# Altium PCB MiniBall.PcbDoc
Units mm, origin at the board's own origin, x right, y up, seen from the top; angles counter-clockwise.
Board outline 43 x 55 mm, 4 copper layers (Top Layer, Plane 1, Plane 2, Bottom Layer), stack 0.781 mm thick; 44 components, 24 nets, 153 pads, 113 vias.
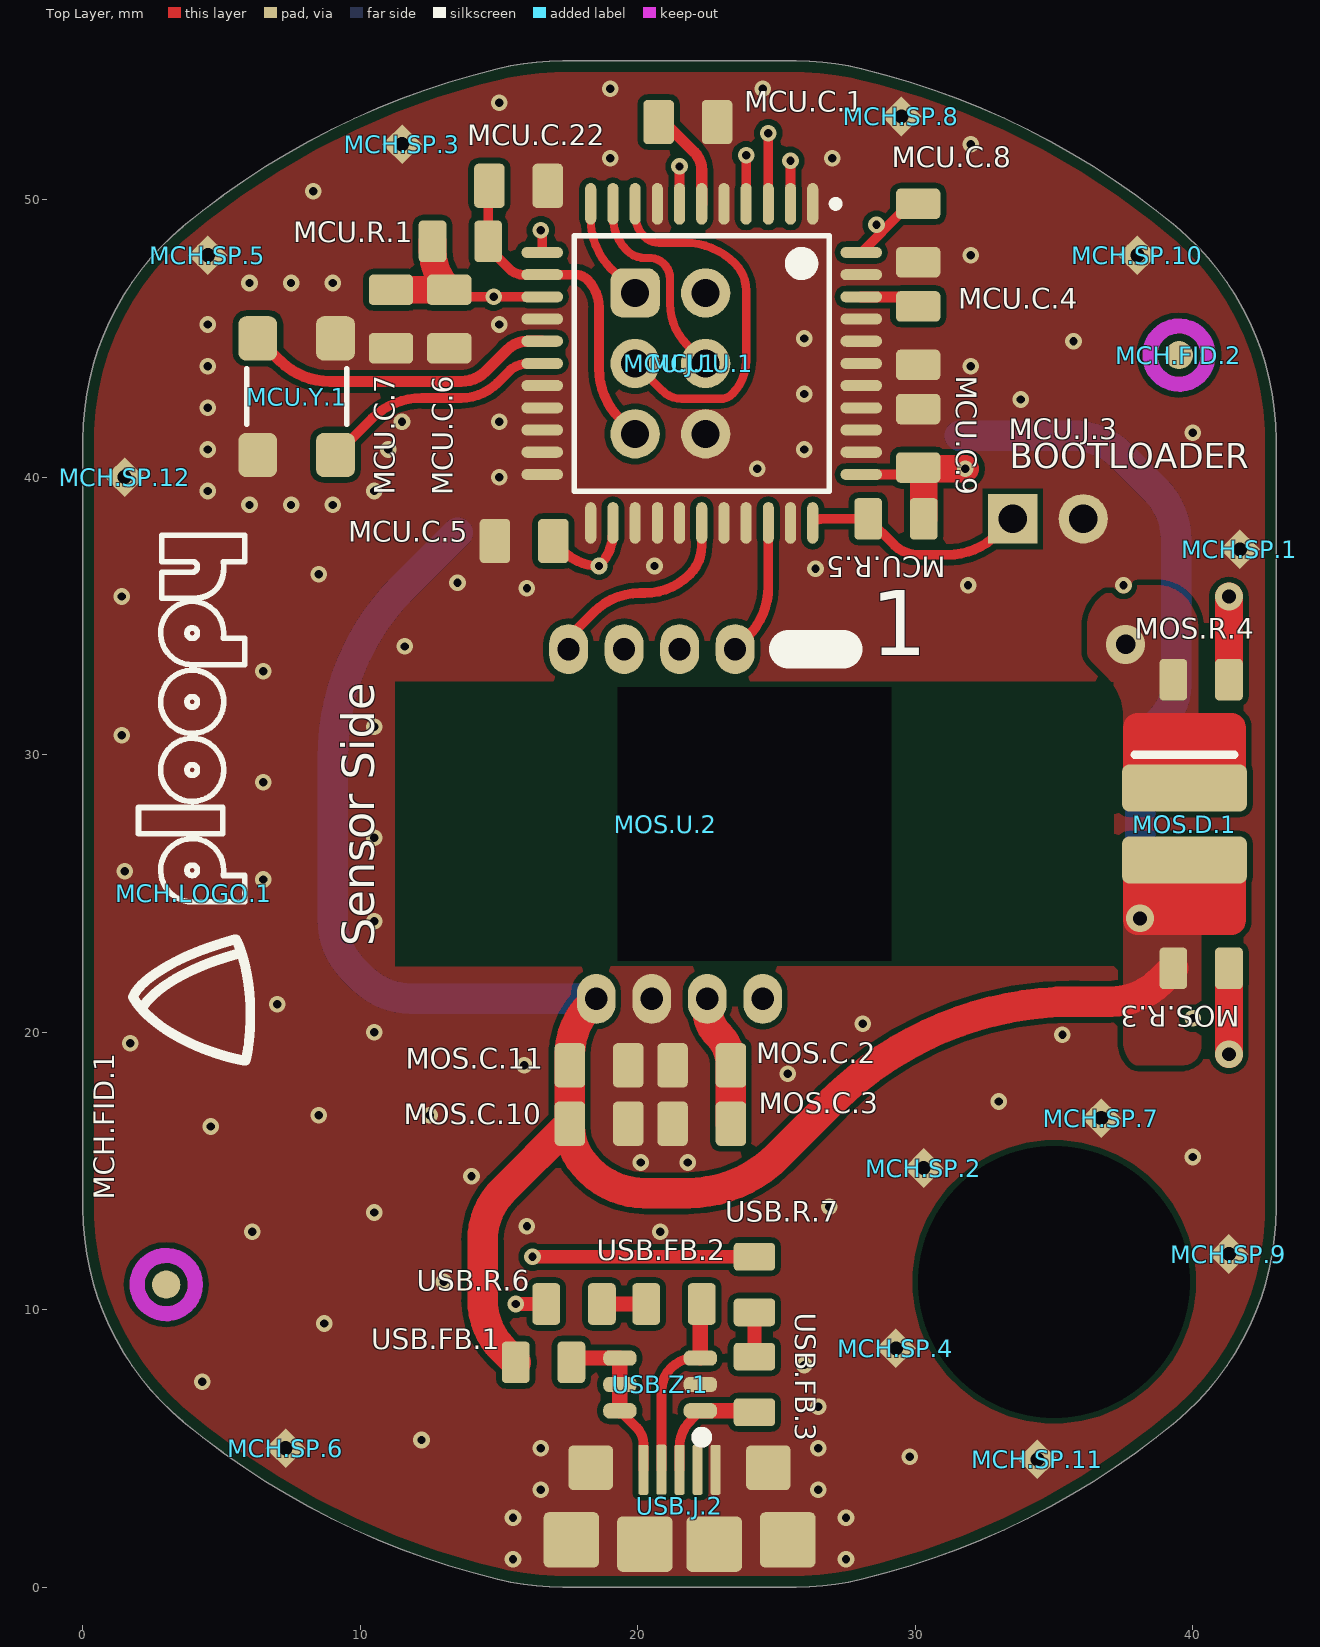
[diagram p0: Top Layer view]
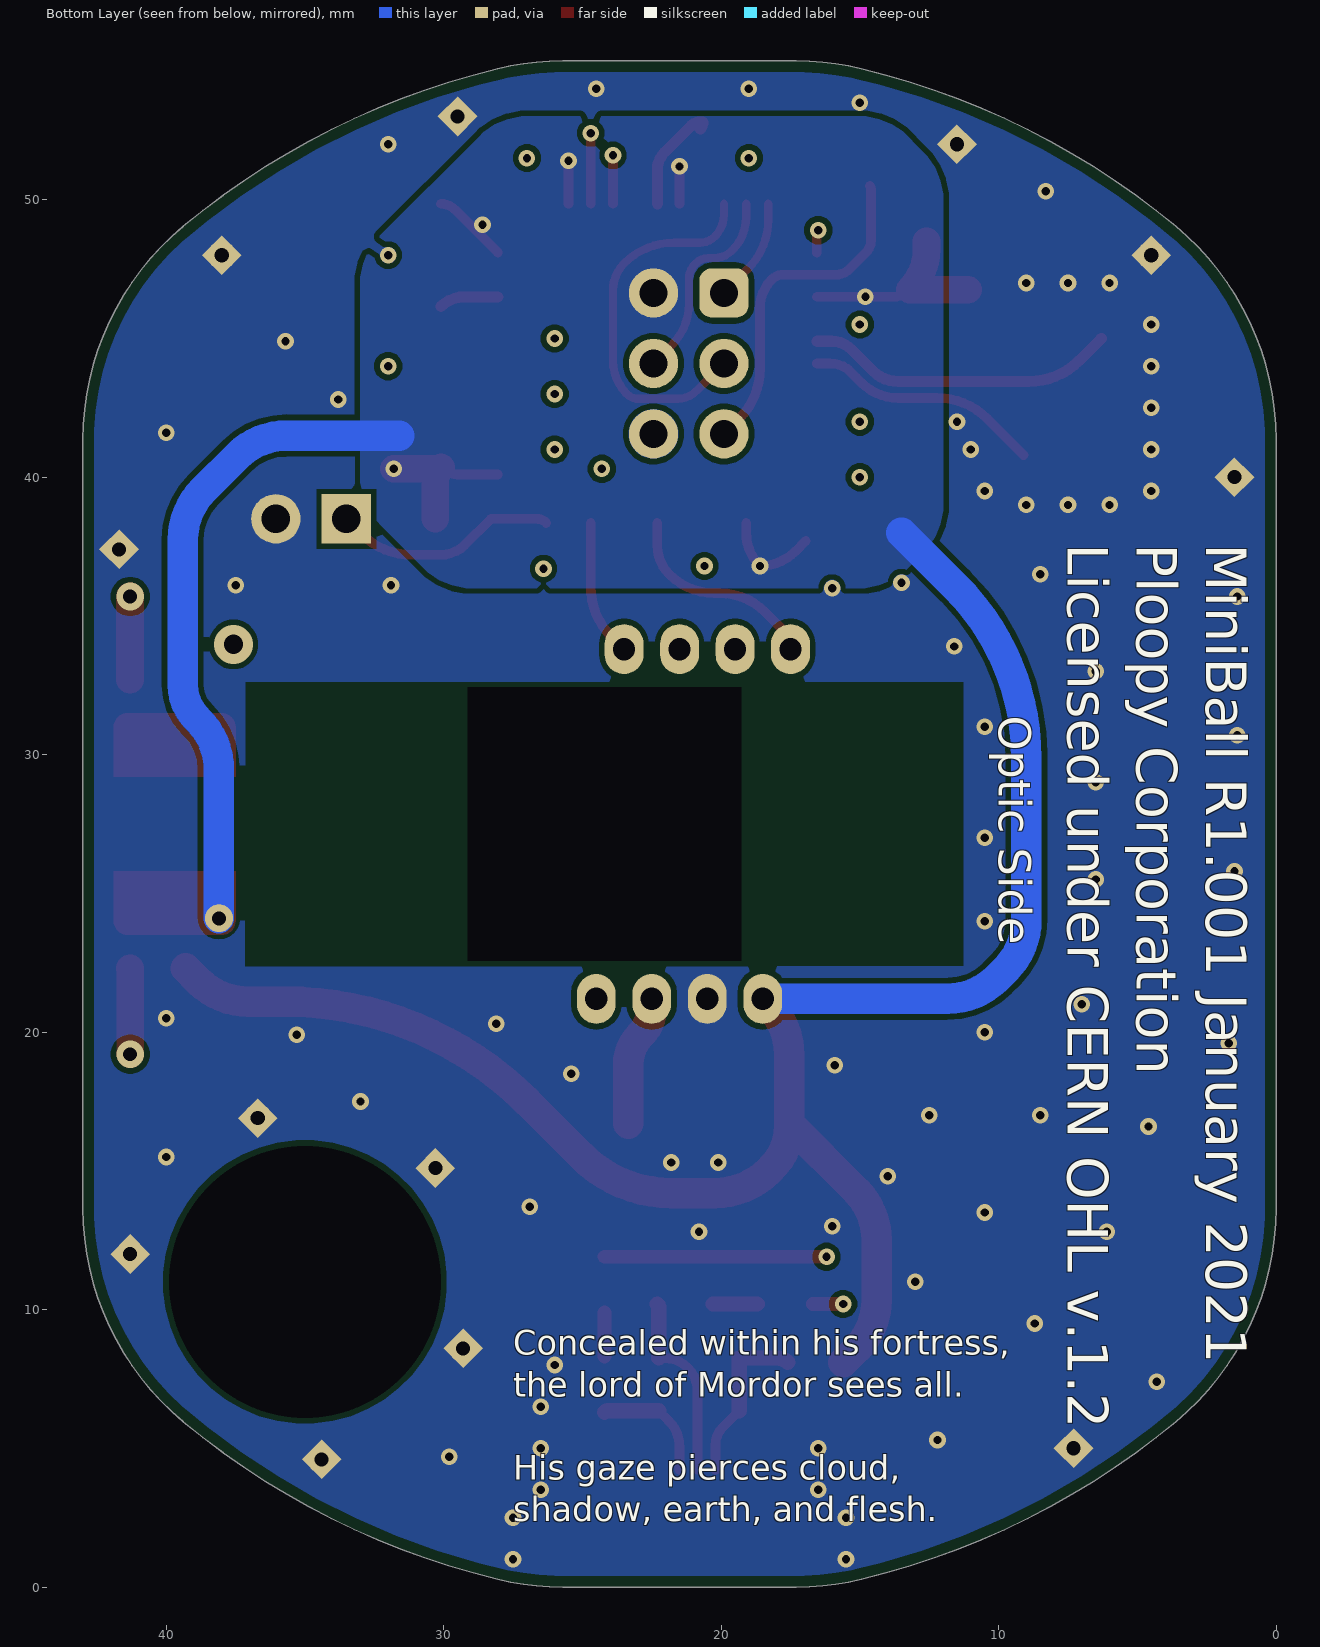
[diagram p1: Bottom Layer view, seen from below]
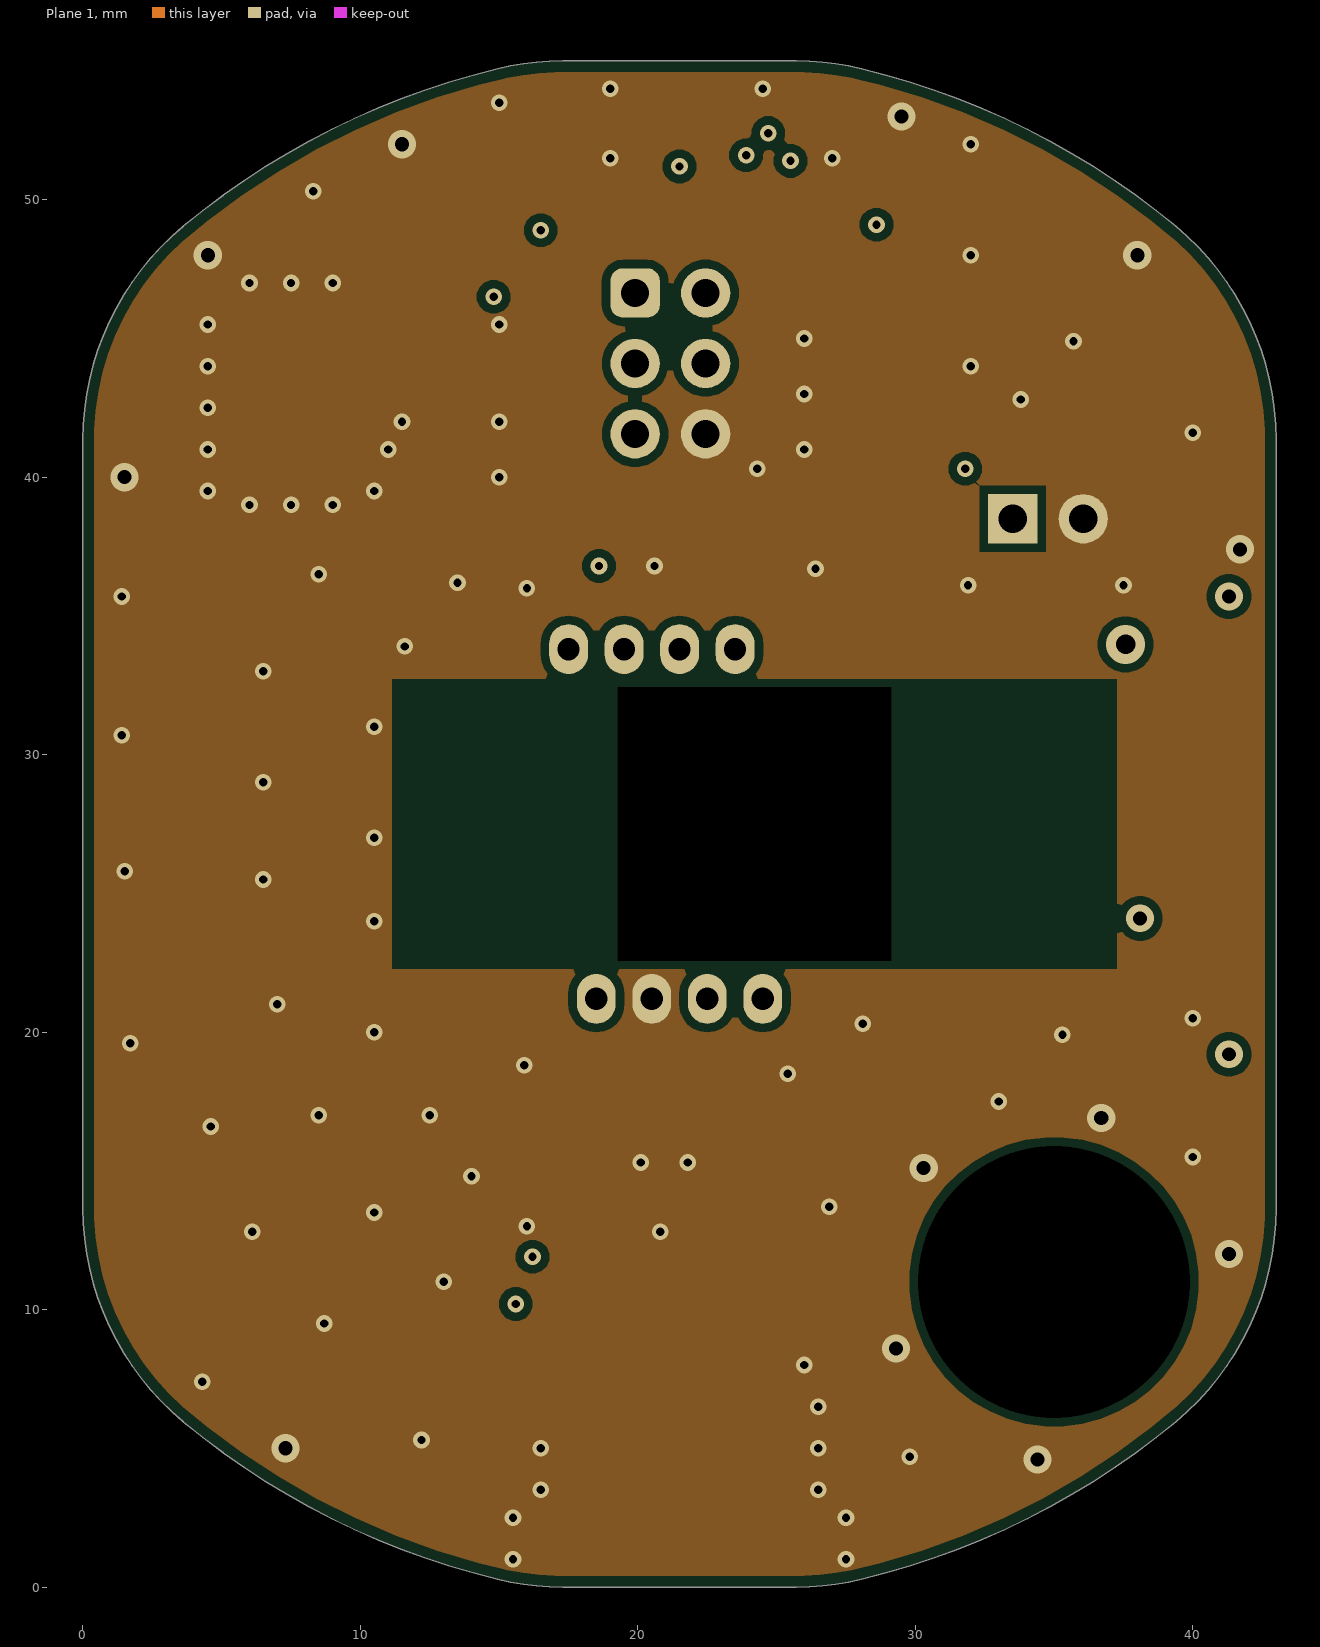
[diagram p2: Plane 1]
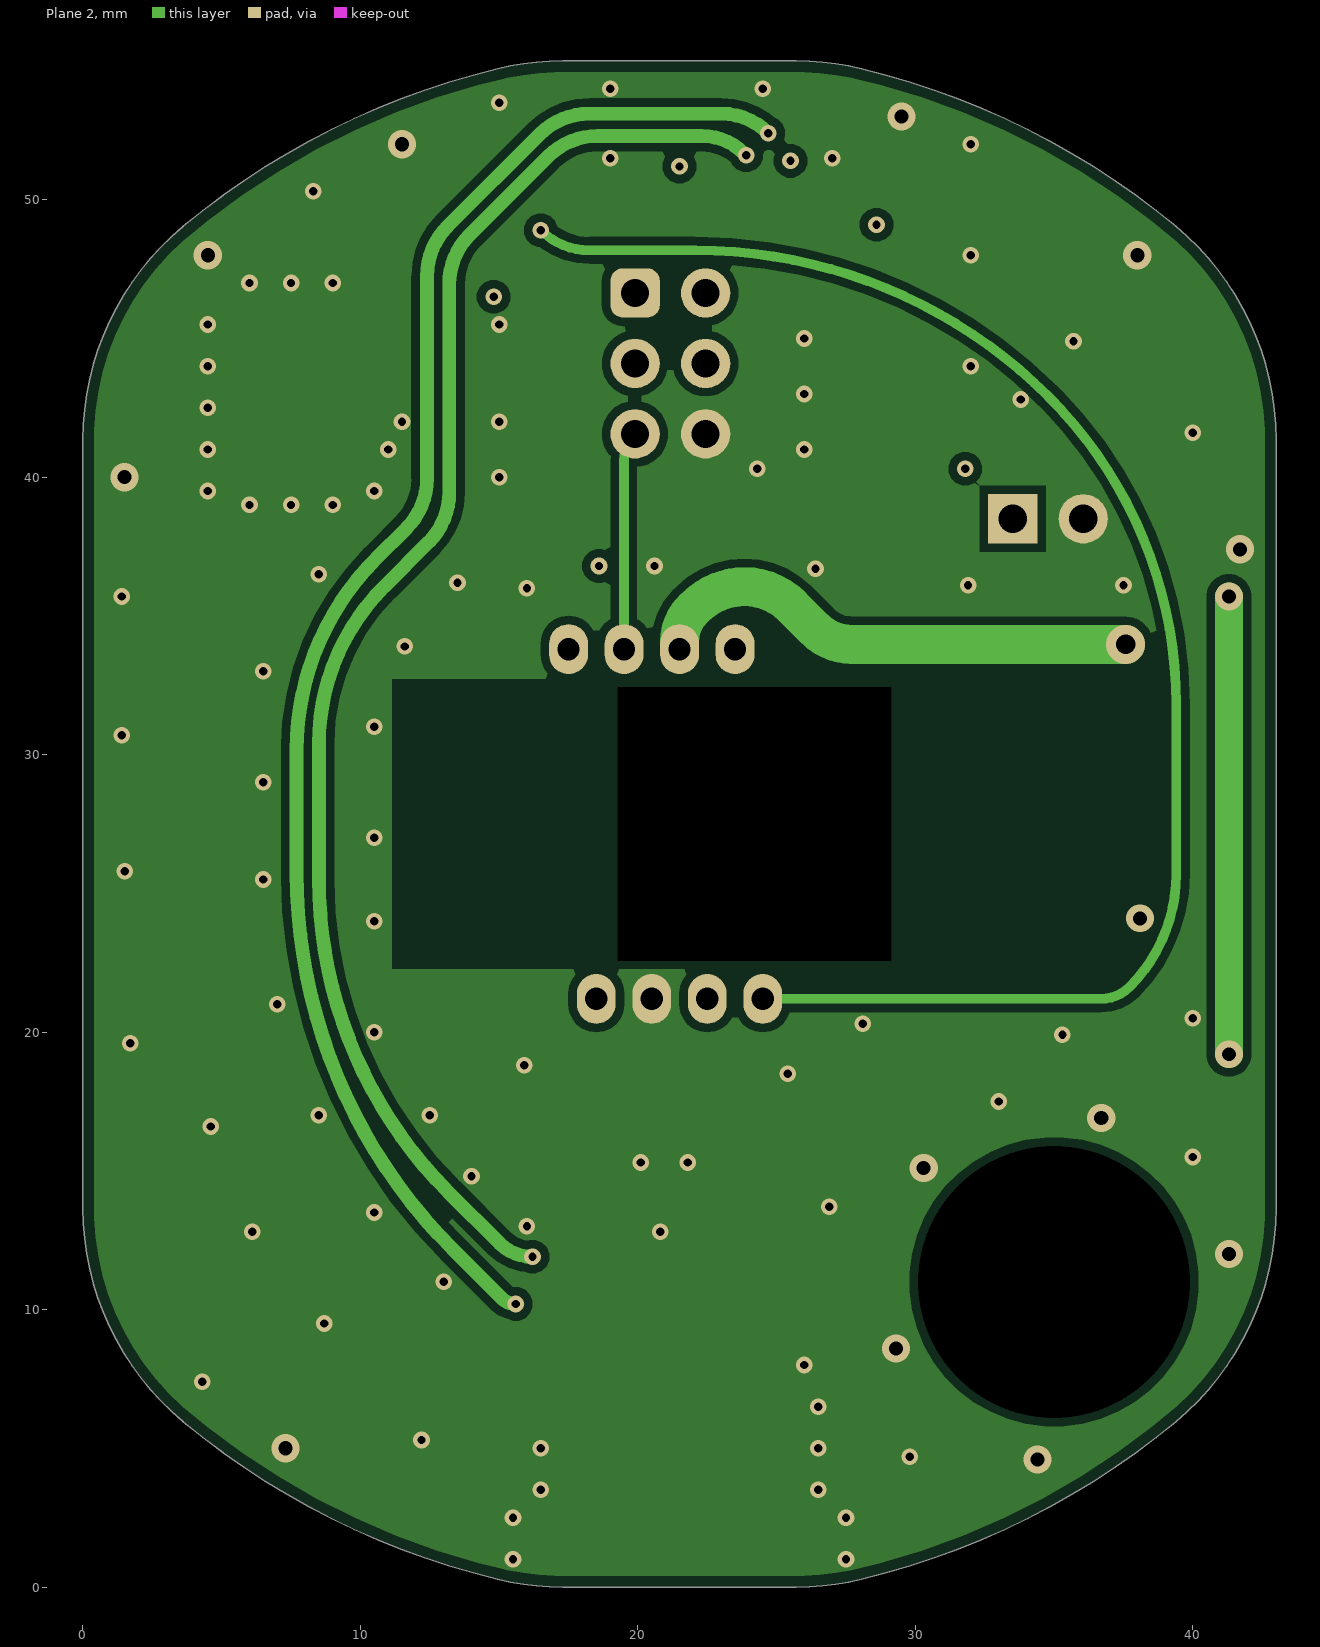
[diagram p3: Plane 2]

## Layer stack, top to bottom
Top Mask: solder mask 0.01, Solder Resist, Dk 3.5
Top Layer: signal copper 0.036
Dielectric 1: prepreg 0.127, FR-4, Dk 4.2
Plane 1: signal copper 0.036
Dielectric 4: core 0.383, Dk 4.2
Plane 2: signal copper 0.036
Dielectric 2: prepreg 0.127, Dk 4.2
Bottom Layer: signal copper 0.036
Bottom Solder: solder mask 0.01, Solder Resist, Dk 3.5

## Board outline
3.611,5.96 ccw(c21.5,27.5) 14.946,0.278 ccw(c17.287,10) 17.287,0 25.713,0 ccw(c25.713,10) 28.054,0.278 ccw(c21.5,27.5) 39.389,5.96 ccw(c33,13.653) 43,13.653 43,41.347 ccw(c33,41.347) 39.389,49.04 ccw(c21.5,27.5) 28.054,54.722 ccw(c25.713,45) 25.713,55 17.287,55 ccw(c17.287,45) 14.946,54.722 ccw(c21.5,27.5) 3.611,49.04 ccw(c10,41.347) 0,41.347 0,13.653 ccw(c10,13.653)

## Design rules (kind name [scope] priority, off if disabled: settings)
BoardOutlineClearance [(Not HasFootprint('SPARKGAP'))] p1: gap=0.4 ignorepadtopadclearanceinfootprint=FALSE except(0: Arc-SplitBarrior Arc-SplitContinuation Track-SplitBarrior Track-SplitContinuation SMDPad-SplitBarrior SMDPad-SplitContinuation THPad-SplitBarrior THPad-SplitContinuation Via-SplitBarrior Via-SplitContinuation Fill-SplitBarrior Fill-SplitContinuation Poly-SplitBarrior Poly-SplitContinuation Region-SplitBarrior Region-SplitContinuation Text-SplitBarrior Text-SplitContinuation)
Clearance "HighV Pads" [(InNetClass('HighV') AND (IsPad OR IsVia)) vs IsPad OR IsVia] p1: gap=0.4 ignorepadtopadclearanceinfootprint=FALSE except(0: Arc-Hole Track-Hole SMDPad-Hole THPad-Hole Via-Hole Fill-Hole Poly-Hole Region-Hole Text-Hole) // Establishes minimum clearance between bare pads that are high voltage, per IPC2221A Table 6-1, 51-100V, condition A6
Clearance Inter-Pad [IsPad vs IsPad] p2: gap=0.2 ignorepadtopadclearanceinfootprint=FALSE except(0: Arc-Hole Track-Hole SMDPad-Hole THPad-Hole Via-Hole Fill-Hole Poly-Hole Region-Hole Text-Hole)
Clearance "Spark Gaps" [InNetClass('Spark Gap') vs InNet('GND') And InPoly] p3: gap=0.635 ignorepadtopadclearanceinfootprint=FALSE except(0: Arc-Hole Track-Hole SMDPad-Hole THPad-Hole Via-Hole Fill-Hole Poly-Hole Region-Hole Text-Hole)
Clearance FIDs [Name like 'FID*'] p4: gap=1.016 ignorepadtopadclearanceinfootprint=FALSE except(0: Arc-Hole Track-Hole SMDPad-Hole THPad-Hole Via-Hole Fill-Hole Poly-Hole Region-Hole Text-Hole)
Clearance "Inner Planes" [InPoly AND OnMid] p5: gap=0.3 ignorepadtopadclearanceinfootprint=FALSE except(0: Arc-Hole Track-Hole SMDPad-Hole THPad-Hole Via-Hole Fill-Hole Poly-Hole Region-Hole Text-Hole) // Defines a larger clearance for planes on inner layers.
Clearance "All Planes" [InPoly] p6: gap=0.2 ignorepadtopadclearanceinfootprint=FALSE except(0: Arc-Hole Track-Hole SMDPad-Hole THPad-Hole Via-Hole Fill-Hole Poly-Hole Region-Hole Text-Hole) // Defines minimum clearance between planes on the same layer.
Clearance "Inner Layer Clearance" [OnMid vs OnMid] p7: gap=0.22 ignorepadtopadclearanceinfootprint=FALSE // We will give inner layers more spacing because they tend to be subject to stricter process limits.
Clearance [All] p8: gap=0.22 ignorepadtopadclearanceinfootprint=FALSE except(0: Arc-Hole Track-Hole SMDPad-Hole THPad-Hole Via-Hole Fill-Hole Poly-Hole Region-Hole Text-Hole) // 2 oz (70um) boards require at least 10mil spacing. We give a bit more to make sure things work well.
ComponentClearance "Terminal Block" [(HasFootprint('Phoenix 1933189 - Header')) vs (HasFootprint('Phoenix 1933189 - Header'))] p1: gap=-2.286 collisioncheckmode=3 verticalgap=0.254 showdistances=FALSE
ComponentClearance "FET/TP self Clearance" [(Name like 'Q*') Or (Name like 'TP*') vs (Name like 'Q*') Or (Name like 'TP*')] p2: gap=0.254 collisioncheckmode=3 verticalgap=0.254 showdistances=FALSE
ComponentClearance [Not ((Name like 'H*') Or (Name like 'FID*') Or (Name like 'SP*')) vs Not ((Name like 'H*') Or (Name like 'FID*') Or (Name like 'SP*'))] p3: gap=0.5 collisioncheckmode=3 verticalgap=0.5 showdistances=FALSE
DiffPairsRouting [All] p1: maxlimit=0.508 minlimit=0.279 mostfreqgap=0.381 substack1={769A8C6D-1C2C-4ABD-9F78-73D1337B8DA3} toplayer_{769a8c6d-1c2c-4abd-9f78-73d1337b8da3}_minwidth=0.381 toplayer_{769a8c6d-1c2c-4abd-9f78-73d1337b8da3}_maxwidth=0.381 toplayer_{769a8c6d-1c2c-4abd-9f78-73d1337b8da3}_prefwidth=0.381 midlayer2_{769a8c6d-1c2c-4abd-9f78-73d1337b8da3}_minwidth=0.381 midlayer2_{769a8c6d-1c2c-4abd-9f78-73d1337b8da3}_maxwidth=0.381 midlayer2_{769a8c6d-1c2c-4abd-9f78-73d1337b8da3}_prefwidth=0.381 midlayer3_{769a8c6d-1c2c-4abd-9f78-73d1337b8da3}_minwidth=0.381 midlayer3_{769a8c6d-1c2c-4abd-9f78-73d1337b8da3}_maxwidth=0.381 midlayer3_{769a8c6d-1c2c-4abd-9f78-73d1337b8da3}_prefwidth=0.381 bottomlayer_{769a8c6d-1c2c-4abd-9f78-73d1337b8da3}_minwidth=0.381 bottomlayer_{769a8c6d-1c2c-4abd-9f78-73d1337b8da3}_maxwidth=0.381 bottomlayer_{769a8c6d-1c2c-4abd-9f78-73d1337b8da3}_prefwidth=0.381 toplayer_prefgap=0.279 toplayer_minwidth=0.279 toplayer_maxwidth=0.508 toplayer_prefwidth=0.381 midlayer2_mingap=0.305 midlayer2_minwidth=0.305 midlayer2_maxwidth=0.508 midlayer2_prefwidth=0.381 midlayer3_prefgap=0.279 midlayer3_minwidth=0.279 midlayer3_maxwidth=0.508 midlayer3_prefwidth=0.381 bottomlayer_prefgap=0.279 bottomlayer_minwidth=0.279 bottomlayer_maxwidth=0.508 bottomlayer_prefwidth=0.381 maxuncoupledlength=12.7
Height [All] p1: minheight=0 maxheight=41 prefheight=12.7
HoleSize [All] p1: absolutevalues=TRUE maxlimit=100 minlimit=0.3 maxpercent=80.000 minpercent=20.000
HoleToHoleClearance [All] p1: gap=0.6 allowstackedmicrovias=TRUE
LayerPairs [All] p1: enforce=FALSE
MinimumSolderMaskSliver [All] p1: minsoldermaskwidth=0.09
NetAntennae [Not (HasFootprint('BALANCE_RESISTOR'))] p1: netantennaetolerance=0
PasteMaskExpansion [All] p1: expansion=-0.025
PlaneClearance [All] p1: clearance=0.3
PlaneConnect [All] p1: pad.planeconnectstyle=Relief pad.reliefexpansion=0.5 pad.reliefentries=4 pad.reliefconductorwidth=0.5 pad.reliefairgap=0.25 via.planeconnectstyle=Direct via.reliefexpansion=0.5 via.reliefentries=4 via.reliefconductorwidth=0.5 via.reliefairgap=0.25
PolygonConnect "PolygonConnect Spark Gap" [HasFootprint('SparkGap')] p1: connectstyle=Direct reliefconductorwidth=0.254 reliefentries=4 polygonreliefangle="90 Angle" airgapwidth=0.254 // This rule makes it so spark gaps get direct connections to ground planes.
PolygonConnect PolygonConnect_GND [All vs InNet('GND')] p2: connectstyle=Direct reliefconductorwidth=0.5 reliefentries=4 polygonreliefangle="90 Angle" airgapwidth=0.25 // This rule specifies all vias and holes connected to a GND plane have direct connections.
PolygonConnect [All] p3: connectstyle=Direct reliefconductorwidth=0.5 reliefentries=4 polygonreliefangle="90 Angle" airgapwidth=0.25
RoutingVias [All] p1: holewidth=0.5 width=1 viastyle="Through Hole" minholewidth=0.2 minwidth=0.5 maxholewidth=5.08 maxwidth=6.35
ShortCircuit [Not (InPadClass('TraceResistorPads')) vs Not (InPadClass('TraceResistorPads'))] p1: allowed=FALSE
SilkToBoardRegionClearance [All] p1 off:
SilkToSilkClearance [All] p1 off: silktosilkclearance=0.254
SilkToSolderMaskClearance SilkscreenOverComponentPads [IsPad] p1: minsilkscreentomaskgap=0.102 clearancetoexposedcopper=FALSE
SolderMaskExpansion [All] p1: expansion=0.076 istentingtop=FALSE
Width [All] p1: maxlimit=50.8 minlimit=0.26 preferedwidth=0.4 substack1={769A8C6D-1C2C-4ABD-9F78-73D1337B8DA3} midlayer2_minwidth=0.35 midlayer3_minwidth=0.35 minimp=50.000000 maximp=50.000000 favimp=50.000000
15 further rules are at their usual default settings.

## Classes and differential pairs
component class USB: USB.FB.1 USB.FB.2 USB.FB.3 USB.J.2 USB.R.6 USB.R.7 USB.Z.1
component class MOS: MOS.C.2 MOS.C.3 MOS.C.10 MOS.C.11 MOS.D.1 MOS.R.3 MOS.R.4 MOS.U.2
component class MCU: MCU.C.1 MCU.C.4 MCU.C.5 MCU.C.6 MCU.C.7 MCU.C.8 MCU.C.9 MCU.C.22 MCU.J.1 MCU.J.3 MCU.R.1 MCU.R.5 MCU.U.1 MCU.Y.1
component class MCH: MCH.FID.1 MCH.FID.2 MCH.LOGO.1 MCH.SP.1 MCH.SP.2 MCH.SP.3 MCH.SP.4 MCH.SP.5 MCH.SP.6 MCH.SP.7 MCH.SP.8 MCH.SP.9 MCH.SP.10 MCH.SP.11 MCH.SP.12

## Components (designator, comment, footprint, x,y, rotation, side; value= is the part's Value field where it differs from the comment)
MCH.FID.1 "IPC-7351 Fiducial 1mm" FIDUCIAL_1.5 3,10.9 r90 top (schematic designator FID1)
MCH.FID.2 "IPC-7351 Fiducial 1mm" FIDUCIAL_1.5 39.5,44.4 r90 top (schematic designator FID2)
MCH.LOGO.1 "Ploopy logo, silkscreen" PloopyLogo 4,25 r90 top (schematic designator LOGO1)
MCH.SP.1 "Spark Gap" SparkGap 41.7,37.4 r90 top (schematic designator SP1)
MCH.SP.2 "Spark Gap" SparkGap 30.3,15.1 r90 top (schematic designator SP2)
MCH.SP.3 "Spark Gap" SparkGap 11.5,52 r90 top (schematic designator SP3)
MCH.SP.4 "Spark Gap" SparkGap 29.3,8.6 r90 top (schematic designator SP4)
MCH.SP.5 "Spark Gap" SparkGap 4.5,48 r90 top (schematic designator SP5)
MCH.SP.6 "Spark Gap" SparkGap 7.3,5 r90 top (schematic designator SP6)
MCH.SP.7 "Spark Gap" SparkGap 36.7,16.9 r90 top (schematic designator SP7)
MCH.SP.8 "Spark Gap" SparkGap 29.5,53 r90 top (schematic designator SP8)
MCH.SP.9 "Spark Gap" SparkGap 41.3,12 r90 top (schematic designator SP9)
MCH.SP.10 "Spark Gap" SparkGap 38,48 r90 top (schematic designator SP10)
MCH.SP.11 "Spark Gap" SparkGap 34.4,4.6 r90 top (schematic designator SP11)
MCH.SP.12 "Spark Gap" SparkGap 1.5,40 r90 top (schematic designator SP12)
MCU.C.1 "0805" "0805 - TALL" 21.8,52.8 r270 top value="1uF 25V" (schematic designator C1)
MCU.C.4 "0805" "0805 - TALL" 30.1,45.1 r180 top value="0.1uF 100V" (schematic designator C4)
MCU.C.5 "0805" "0805 - TALL" 15.9,37.7 r90 top value="0.1uF 100V" (schematic designator C5)
MCU.C.6 "0805" "0805 - TALL" 13.2,45.7 r180 top value="0.1uF 100V" (schematic designator C6)
MCU.C.7 "0805" "0805 - TALL" 11.1,45.7 r180 top value="10uF 25V" (schematic designator C7)
MCU.C.8 "0805" "0805 - TALL" 30.1,48.8 r180 top value="0.1uF 100V" (schematic designator C8)
MCU.C.9 "0805" "0805 - TALL" 30.1,41.4 r0 top value="0.1uF 100V" (schematic designator C9)
MCU.C.22 "0805" "0805 - TALL" 15.7,50.5 r270 top value="0.1uF 100V" (schematic designator C22)
MCU.J.1 "Atmel_ICSP" 6x2 19.9,46.64 r0 top (schematic designator J1)
MCU.J.3 "HEADER2" 2x1 33.51,38.5 r90 top (schematic designator J3)
MCU.R.1 "0805" 0805 13.6,48.5 r270 top value="10k 1%" (schematic designator R1)
MCU.R.5 "0805" 0805 29.3,38.5 r90 top value="10k 1%" (schematic designator R5)
MCU.U.1 "ATMEGA32U4RC-AU" "ATmega32U4 - TQFP80P1200X1200X120-44N" 22.3,44.1 r270 top (schematic designator U1)
MCU.Y.1 "ECS-160-12-30B-AGM" LFXTAL055663BULK 7.7,42.9 r270 top (schematic designator Y1)
MOS.C.2 "0805" "0805 - TALL" 22.3,18.8 r90 top value="0.1uF 100V" (schematic designator C2)
MOS.C.3 "0805" "0805 - TALL" 22.3,16.7 r90 top value="1uF 25V" (schematic designator C3)
MOS.C.10 "0805" "0805 - TALL" 18.6,16.7 r270 top value="10uF 25V" (schematic designator C10)
MOS.C.11 "0805" "0805 - TALL" 18.6,18.8 r270 top value="0.1uF 100V" (schematic designator C11)
MOS.D.1 "SIDELED-A67F" SIDELED-A67F 39.4,27.5 r0 top (schematic designator D1)
MOS.R.3 "0805" 0805 40.3,22.3 r270 top value="22R 1%" (schematic designator R3)
MOS.R.4 "0805" 0805 40.3,32.7 r90 top value="22R 1%" (schematic designator R4)
MOS.U.2 "ADNS-5050" ADNS-5050 23.5,33.8 r0 top locked (schematic designator U2)
USB.FB.1 "ACML-0805-601-T" 0805 16.6,8.1 r270 top value="Ferrite Bead 600R" (schematic designator FB1)
USB.FB.2 "ACML-0805-601-T" 0805 21.3,10.2 r270 top value="Ferrite Bead 600R" (schematic designator FB2)
USB.FB.3 "ACML-0805-601-T" 0805 24.2,7.3 r180 top value="Ferrite Bead 600R" (schematic designator FB3)
USB.J.2 "10118192-0001LF" 10118192-0001LF 21.5,0.4 r180 top (schematic designator J2)
USB.R.6 "0805" 0805 17.7,10.2 r270 top value="22R 1%" (schematic designator R6)
USB.R.7 "0805" 0805 24.2,10.9 r180 top value="22R 1%" (schematic designator R7)
USB.Z.1 "IP4220CZ6,125" "PESD3V3S4UD - SOT95P275X110-6N" 20.8,7.3 r180 top (schematic designator Z1)

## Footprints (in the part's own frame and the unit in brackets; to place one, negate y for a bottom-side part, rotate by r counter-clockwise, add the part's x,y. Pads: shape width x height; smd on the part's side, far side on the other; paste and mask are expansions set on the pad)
2x1 [mil]
  rect 70x70 hole 40 paste-3897.64: 1(0,0)
  round 70 hole 40 paste-3897.64: 2(0,-100)
  body extent -50,-150 50,50, height 339
6x2 [mil]
  rrect50% 70x70 hole 40 paste-3897.64: 1(0,0)
  round 70 hole 40 paste-3897.64: 2(100,0) 3(0,-100) 4(100,-100) 5(0,-200) 6(100,-200)
  body extent -50,-250 150,50, height 330
0805 [mm] "Chip Capacitor, 2-Leads, Body 2.0x1.3mm, IPC Medium Density"
  rrect30% 1.5x1 smd paste-0.04: 1(0,1.002) 2(0,-1.002)
  body extent -0.72,-1.1 0.72,1.1, height 0.8
"0805 - TALL" [mm] "Same as 0805 footprint, but solder mask is adjusted to leave more paste behind for tall (>0.9mm) components like big caps, which tend to be solder-starved on the regular footprint."
  rrect30% 1.6x1.1 smd paste-0.04: 1(0,1.052) 2(0,-1.052)
  body extent -0.72,-1.1 0.72,1.1, height 0.8
10118192-0001LF [mm]
  rrect30% 0.35x1.8 smd paste-0.04 mask+0.07: 1(1.3,-3.825) 2(0.65,-3.828) 3(0,-3.825) 4(-0.65,-3.825) 5(-1.3,-3.825)
  rrect20% 2x2 smd paste-0.3: 6(-3.9,-1.3) 6(-1.25,-1.147) 6(1.25,-1.147) 6(3.9,-1.3)
  rrect20% 1.6x1.6 smd paste-0.3: 6(-3.2,-3.9) 6(3.2,-3.9)
  body extent -3.96,-4.36 3.96,1.3, height 2.79
ADNS-5050 [mm]
  oval 1.4x1.8 hole 0.8: 1(0,0) 2(-2,0) 3(-4,0) 4(-6,0) 5(-5,-12.6) 6(-3,-12.6) 7(-1,-12.6) 8(1,-12.6)
  rect 0x0 hole 9.85 square unplated: ""(0.7,-6.3)
  silkscreen extent 1.92,0 3.9,0, body extent -15,-14.3 15,1.7, height 5.45
"ATmega32U4 - TQFP80P1200X1200X120-44N" [mm] "TQFP, 44-Leads, Body 10.00x10.00mm, Pitch 0.80mm, IPC Medium Density"
  rrect100% 1.5x0.4 smd paste-0.06: 1(-5.75,4) 2(-5.75,3.2) 3(-5.75,2.4) 4(-5.75,1.6) 5(-5.75,0.8) 6(-5.75,0) 7(-5.75,-0.8) 8(-5.75,-1.6) 9(-5.75,-2.4) 10(-5.75,-3.2) 11(-5.75,-4) 23(5.75,-4) 24(5.75,-3.2) 25(5.75,-2.4) 26(5.75,-1.6) 27(5.75,-0.8) 28(5.75,0) 29(5.75,0.8) 30(5.75,1.6) 31(5.75,2.4) 32(5.75,3.2) 33(5.75,4)
  rrect100% 0.4x1.5 smd paste-0.06: 12(-4,-5.75) 13(-3.2,-5.75) 14(-2.4,-5.75) 15(-1.6,-5.75) 16(-0.8,-5.75) 17(0,-5.75) 18(0.8,-5.75) 19(1.6,-5.75) 20(2.4,-5.75) 21(3.2,-5.75) 22(4,-5.75) 34(4,5.75) 35(3.2,5.75) 36(2.4,5.75) 37(1.6,5.75) 38(0.8,5.75) 39(0,5.75) 40(-0.8,5.75) 41(-1.6,5.75) 42(-2.4,5.75) 43(-3.2,5.75) 44(-4,5.75)
  silkscreen extent -5.87,-4.6 4.6,4.95, body extent -5,-5 5,5, height 1.2
FIDUCIAL_1.5 [mil]
  round 40 smd paste-60 mask+30: 1(0,0)
  Top Layer keep-out circle w21.65: c0,0 r41.34
LFXTAL055663BULK [mm]
  rrect40% 1.6x1.4 smd paste-0.05: 1(-2.1,-1.4) 2(2.1,-1.4) 3(2.1,1.4) 4(-2.1,1.4)
  silkscreen extent -1,-1.8 1,1.8, body extent -2.5,-1.6 2.5,1.6, height 1
"PESD3V3S4UD - SOT95P275X110-6N" [mm] "SOT23, 6-Leads, Body 2.90x2.75mm, Pitch 0.95mm, IPC Medium Density"
  rrect80% 1.2x0.55 smd paste-0.045 mask+0.085: 1(-1.45,0.95) 2(-1.45,0) 3(-1.45,-0.95) 4(1.45,-0.95) 5(1.45,0) 6(1.45,0.95)
  silkscreen extent -1.63,1.78 -1.38,2.02, body extent -0.85,-1.55 0.85,1.55, height 1.1
PloopyLogo [mm]
  silkscreen extent -6.04,-2.03 12.9,2.2
SIDELED-A67F [mm]
  rrect30% 4.5x1.7 smd paste-0.04: A(0.3,-1.3) C(0.3,1.3)
  Top Layer region: 2.5,-1.7 2.5,-3.5 2.462,-3.691 2.354,-3.854 2.191,-3.962 2,-4 2,-4 -1.4,-4 -1.591,-3.962 -1.754,-3.854 -1.862,-3.691 -1.9,-3.5 -1.9,-3.5 -1.9,-1.7
  Top Layer region: -1.9,1.7 -1.9,3.5 -1.862,3.691 -1.754,3.854 -1.591,3.962 -1.4,4 -1.4,4 2,4 2.191,3.962 2.354,3.854 2.462,3.691 2.5,3.5 2.5,3.5 2.5,1.7
  silkscreen extent -1.5,2.5 2.1,2.5, body extent -1.56,-2 2.2,2, height 4.03
SparkGap [mil]
  rect 40x40 smd rot 45 paste-99 mask+4: 1(0,0)
  rect 40x40 smd far side rot 45 paste-99 mask+4: 1(0,0)

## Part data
MCH.FID.1 MCH.FID.2: library part FIDUCIAL_1.5
MCH.LOGO.1: library part PloopyLogo
MCH.SP.1 MCH.SP.2 MCH.SP.3 MCH.SP.4 MCH.SP.5 MCH.SP.6 MCH.SP.7 MCH.SP.8 MCH.SP.9 MCH.SP.10 MCH.SP.11 MCH.SP.12: "Open square pad for spark gapping"
MCU.C.1 MOS.C.3: library part "Cap 1uF 25V", "0805, X5R or better", Supplier Part Number 1=1276-1066-2-ND
MCU.C.4 MCU.C.5 MCU.C.6 MCU.C.8 MCU.C.9 MCU.C.22 MOS.C.2 MOS.C.11: library part "Cap 0.1uF 100V", "0805, X5R or better", Supplier Part Number 1=1276-6840-2-ND
MCU.C.7 MOS.C.10: library part "Cap 10uF 25V", "0805, X5R or better", Supplier Part Number 1=81-GRM21BR61E106KA3L
MCU.J.1: "6-pin 0.100\" ICSP header", Supplier Part Number 1=S2012EC-03-ND
MCU.J.3: "2-pin 0.100\" header", Supplier Part Number 1=855-M20-9990245
MCU.R.1 MCU.R.5: library part "Res 10k 1% 0805", "Chip resistor", Supplier Part Number 1=RMCF0805FT10K0TR-ND
MCU.U.1: "IC MCU 8BIT 32KB FLASH 44TQFP", Supplier Part Number 1=ATMEGA32U4RC-AU-ND
MCU.Y.1: "16MHz Crystal 12pF 100 Ohms 4-SMD, No Lead", Supplier Part Number 1=XC2686CT-ND
MOS.D.1: "Red/Orange/Yellow Side-facing SMT LEDs, high brightness (~2lm)", Supplier Part Number 1=475-3392-1-ND
MOS.R.3 MOS.R.4 USB.R.6 USB.R.7: library part "Res 22R 1% 0805", "Chip resistor", Supplier Part Number 1=RMCF0805FT22R0CT-ND
MOS.U.2: "Optical Mouse Navigation Sensor"
USB.FB.1 USB.FB.2 USB.FB.3: "FERRITE BEAD 600 OHM 0805 1LN", Supplier Part Number 1=535-12556-1-ND
USB.J.2: "CONN RCPT USB2.0 MICRO B SMD R/A"
USB.Z.1: "TVS DIODE 5.5V 6TSOP (Low capacitance, USB)", Supplier Part Number 1=1727-3578-1-ND

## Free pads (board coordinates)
  round 0 hole 9.8: ""(35,11)

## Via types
v1: diameter 0.6, hole 0.3, Top Layer to Bottom Layer, tented both sides, 97 vias
v2: diameter 1.016, hole 0.508, Top Layer to Bottom Layer, tented both sides, 12 vias
v3: diameter 1, hole 0.5, Top Layer to Bottom Layer, tented both sides, 3 vias
v4: diameter 1.4, hole 0.7, Top Layer to Bottom Layer, tented both sides, 1 vias

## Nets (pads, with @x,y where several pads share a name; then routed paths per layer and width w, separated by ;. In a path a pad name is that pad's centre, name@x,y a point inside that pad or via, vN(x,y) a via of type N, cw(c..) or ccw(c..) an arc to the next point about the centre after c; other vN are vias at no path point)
GND: MCH.SP.1.1 MCH.SP.2.1 MCH.SP.3.1 MCH.SP.4.1 MCH.SP.5.1 MCH.SP.6.1 MCH.SP.7.1 MCH.SP.8.1 MCH.SP.9.1 MCH.SP.10.1 MCH.SP.11.1 MCH.SP.12.1 MCU.C.1.1 MCU.C.4.1 MCU.C.5.1 MCU.C.6.1 MCU.C.7.1 MCU.C.8.1 MCU.C.9.1 MCU.C.22.1 MCU.J.1.6 MCU.J.3.2 MCU.U.1.1 MCU.U.1.5 MCU.U.1.8 MCU.U.1.15 MCU.U.1.18 MCU.U.1.19 MCU.U.1.20 MCU.U.1.21 MCU.U.1.22 MCU.U.1.23 MCU.U.1.25 MCU.U.1.26 MCU.U.1.27 MCU.U.1.29 MCU.U.1.30 MCU.U.1.32 MCU.U.1.35 MCU.U.1.36 MCU.U.1.37 MCU.U.1.38 MCU.U.1.39 MCU.U.1.40 MCU.U.1.41 MCU.U.1.43 MCU.Y.1.2 MCU.Y.1.4 MOS.C.2.1 MOS.C.3.1 MOS.C.10.1 MOS.C.11.1 MOS.U.2.6 USB.J.2.5 USB.J.2.6 USB.Z.1.2
  other v1: 15.5,1 27.5,1 15.5,2.5 27.5,2.5 16.5,3.5 26.5,3.5 29.8,4.7 16.5,5 26.5,5 12.2,5.3 26.5,6.5 4.3,7.4 26,8 8.7,9.5 13,11 6.1,12.8 20.8,12.8 16,13 10.5,13.5 26.9,13.7 14,14.8 20.1,15.3 21.8,15.3 40,15.5 4.6,16.6 8.5,17 12.5,17 33,17.5 25.4,18.5 15.9,18.8 1.7,19.6 35.3,19.9 10.5,20 28.1,20.3 40,20.5 7,21 10.5,24 6.5,25.5 1.5,25.8 10.5,27 6.5,29 1.4,30.7 10.5,31 6.5,33 11.6,33.9 1.4,35.7 16,36 31.9,36.1 37.5,36.1 13.5,36.2 8.5,36.5 26.4,36.7 20.6,36.8 6,39 7.5,39 9,39 4.5,39.5 10.5,39.5 15,40 24.3,40.3 4.5,41 11,41 26,41 40,41.6 11.5,42 15,42 4.5,42.5 33.8,42.8 26,43 4.5,44 32,44 35.7,44.9 26,45 4.5,45.5 15,45.5 6,47 7.5,47 9,47 32,48 8.3,50.3 19,51.5 27,51.5 32,52 15,53.5 19,54 24.5,54
  other v2: 34.4,4.6 7.3,5 29.3,8.6 41.3,12 30.3,15.1 36.7,16.9 41.7,37.4 1.5,40 4.5,48 38,48 11.5,52 29.5,53
MISO: MCU.J.1.1 MCU.U.1.11 | length 3.8
  Top Layer w0.3: MCU.U.1.11 18.3,49.292 ccw(c20.84,49.292) 19.044,47.496 MCU.J.1.1
MOSI: MCU.J.1.4 MCU.U.1.10 | length 7.4
  Top Layer w0.3: MCU.U.1.10 19.1,49.382 ccw(c20.807,49.382) 19.6,48.175 ccw(c20.264,48.839) 20.264,47.9 20.464,47.9 20.48,47.9 cw(c20.407,47.152) 21.159,47.152 21.159,46.25 ccw(c23.257,46.25) 21.773,44.767 MCU.J.1.4
NetMCU.C.1_2: MCU.C.1.2 MCU.U.1.6 | length 3.9
  Top Layer w0.4: MCU.C.1.2@20.648,52.8 ccw(c21.004,52.8) MCU.C.1.2@20.752,52.548 ; MCU.C.1.2 cw(c20.748,52.311) 21.093,52.657 22.025,51.725 cw(c21.361,51.061) 22.3,51.061 MCU.U.1.6
NetMCU.C.4_2: MCU.C.4.2 MCU.U.1.42 | length 2.1
  Top Layer w0.4: MCU.U.1.42 29.261,46.5 cw(c29.261,45.313) MCU.C.4.2
NetMCU.J.3_1: MCU.J.3.1 MCU.R.5.1 MCU.U.1.33 | length 8.2
  Top Layer w0.35: MCU.U.1.33 cw(c26.662,37.988) 26.662,38.5 MCU.R.5.1 29.242,37.555 ccw(c30.1,38.413) 30.1,37.2 31.158,37.2 ccw(c31.158,39.74) 32.954,37.944 MCU.J.3.1
NetMCU.U.1_3: MCU.U.1.3 USB.R.6.2 | length 60
  Top Layer w0.35: MCU.U.1.3 v1(24.7,52.4)
  Top Layer w0.5: v1(15.6,10.2) USB.R.6.2
  Plane 2 w0.5: 13.331,12.169 15.122,10.378 ccw(c15.552,10.809) 15.552,10.2 v1(15.6,10.2) ; 13.33,12.17 cw(c26.917,25.76) 7.7,25.76 7.7,25.762 7.7,30.152 7.7,30.154 cw(c17.467,30.154) 10.562,37.062 11.656,38.156 ccw(c9.86,39.952) 12.4,39.952 12.4,47.248 cw(c14.94,47.248) 13.144,49.044 16.456,52.356 cw(c18.252,50.56) 18.252,53.1 23.01,53.1 cw(c23.01,50.71) v1(24.7,52.4)
NetMCU.U.1_4: MCU.U.1.4 USB.R.7.2 | length 62.6
  Top Layer w0.35: MCU.U.1.4 v1(23.9,51.6)
  Top Layer w0.5: v1(16.2,11.9) 16.201,11.901 24.199,11.901 USB.R.7.2
  Plane 2 w0.5: v1(16.2,11.9) cw(c16.2,13.59) 15.005,12.395 13.194,14.206 cw(c24.52,25.536) 8.5,25.536 8.5,25.538 8.5,30.376 8.5,30.379 cw(c16.518,30.379) 10.85,36.05 12.456,37.656 ccw(c10.66,39.452) 13.2,39.452 13.2,46.948 cw(c15.74,46.948) 13.944,48.744 16.756,51.556 cw(c18.552,49.76) 18.552,52.3 22.3,52.3 cw(c22.3,50.127) 23.836,51.664 v1(23.9,51.6)
NetMCU.U.1_12: MCU.U.1.12 MOS.U.2.8 | length 57
  Top Layer w0.35: v1(16.5,48.9) cw(c16.379,48.779) 16.55,48.779 MCU.U.1.12
  Plane 2 w0.35: v1(16.5,48.9) ccw(c18.25,50.65) 18.25,48.175 22.073,48.175 22.075,48.175 cw(c22.075,30.189) 34.793,42.907 34.795,42.905 34.806,42.894 ; MOS.U.2.8 36.693,21.2 ccw(c36.693,22.646) 37.714,21.622 ccw(c33.649,25.69) 39.4,25.69 39.4,31.804 39.4,31.806 ccw(c23.722,31.806) 34.807,42.893
NetMCU.U.1_16: MCU.U.1.16 MCU.Y.1.1 | length 11.3
  Top Layer w0.4: MCU.Y.1.1 7.106,44.194 ccw(c8.902,45.99) 8.902,43.45 13.625,43.45 ccw(c13.625,44.717) 14.521,43.821 15.3,44.6 cw(c16.024,43.876) 16.024,44.9 MCU.U.1.16
NetMCU.U.1_17: MCU.U.1.17 MCU.Y.1.3 | length 8.6
  Top Layer w0.35: MCU.Y.1.3 10.411,42.111 cw(c12.207,40.315) 12.207,42.855 13.625,42.855 ccw(c13.625,44.717) 14.943,43.402 15.117,43.576 15.403,43.862 cw(c15.649,43.613) 15.448,43.899 cw(c16.085,42.99) 16.085,44.1 MCU.U.1.17
NetMCU.U.1_28: MCU.U.1.28 MOS.U.2.4 | length 7.5
  Top Layer w0.35: MOS.U.2.4 cw(c18.526,33.8) 17.801,34.526 18.411,35.136 cw(c20.075,33.471) 20.075,35.825 20.245,35.825 ccw(c20.245,38.13) 21.875,36.5 ccw(c20.849,37.526) 22.3,37.526 MCU.U.1.28
NetMCU.U.1_31: MCU.U.1.31 MOS.U.2.1 | length 4.9
  Top Layer w0.35: MOS.U.2.1 23.956,34.256 ccw(c22.16,36.052) 24.7,36.052 MCU.U.1.31
NetMOS.C.2_2: MOS.C.2.2 MOS.C.3.2 MOS.U.2.7 | length 4.7
  Top Layer w1.1: MOS.U.2.7 22.5,20.866 ccw(c23.866,20.866) 22.9,19.9 cw(c21.808,18.808) 23.352,18.808 MOS.C.2.2 MOS.C.3.2
NetMOS.D.1_C: MOS.D.1.C MOS.R.4.1 MOS.U.2.2 | length 18.1
  Plane 2 w1.4: MOS.U.2.2 21.5,34.078 cw(c23.122,34.078) 21.975,35.225 22.058,35.308 cw(c23.854,33.512) 23.854,36.052 cw(c23.854,33.653) 25.551,35.349 26.375,34.525 ccw(c27.703,35.853) 27.703,33.975 v4(37.575,33.975)
NetMOS.R.3_1: MOS.R.3.1 MOS.R.4.2 | length 22.6
  Top Layer w1: v3(41.3,19.2) 41.3,22.298 MOS.R.3.1 ; v3(41.3,35.7) 41.302,35.698 MOS.R.4.2
  Plane 2 w1: v3(41.3,19.2) v3(41.3,35.7)
NetUSB.FB.1_1: USB.FB.1.1 USB.J.2.1 USB.Z.1.4 USB.Z.1.5 USB.Z.1.6 | length 6.1
  Top Layer w0.35: USB.Z.1.6 19.95,5.75 ; 19.95,5.75 cw(c19.346,5.146) 20.2,5.146 USB.J.2.1
  Top Layer w0.55: USB.FB.1.1 cw(c17.965,7.738) 17.965,8.25 USB.Z.1.4 USB.Z.1.5 USB.Z.1.6
NetUSB.FB.2_1: USB.FB.2.1 USB.J.2.2 USB.Z.1.3 | length 6.9
  Top Layer w0.35: USB.J.2.2 20.85,7.055 cw(c22.045,7.055) 21.2,7.9 cw(c22.045,7.055) 22.045,8.25 USB.Z.1.3
  Top Layer w0.55: USB.Z.1.3 22.25,10.073 cw(c22.429,10.073) USB.FB.2.1
NetUSB.FB.2_2: USB.FB.2.2 USB.R.6.1 | length 1.6
  Top Layer w0.55: USB.R.6.1 USB.FB.2.2
NetUSB.FB.3_1: USB.FB.3.1 USB.J.2.3 USB.Z.1.1 | length 4.3
  Top Layer w0.35: USB.J.2.3 21.5,5.034 cw(c22.866,5.034) 21.9,6 USB.Z.1.1
  Top Layer w0.55: USB.Z.1.1 24.073,6.35 cw(c24.073,6.171) USB.FB.3.1
NetUSB.FB.3_2: USB.FB.3.2 USB.R.7.1 | length 1.6
  Top Layer w0.5: USB.FB.3.2 USB.R.7.1
R\E\S\E\T\: MCU.C.22.2 MCU.J.1.5 MCU.R.1.1 MCU.U.1.13 MOS.U.2.3 | length 20.2
  Top Layer w0.35: MCU.C.22.2 ccw(c14.757,50.391) 14.602,50.391 MCU.R.1.1 ccw(c15.151,48.5) 14.763,48.112 15.375,47.5 ccw(c15.858,47.983) 15.858,47.3 MCU.U.1.13 17.753,47.3 cw(c17.753,46.703) 18.175,47.125 cw(c17.149,46.099) 18.6,46.099 18.6,43.912 ccw(c21.14,43.912) 19.344,42.116 MCU.J.1.5
  Plane 2 w0.35: MOS.U.2.3 19.5,40.594 cw(c20.866,40.594) MCU.J.1.5
SCLK: MCU.J.1.3 MCU.U.1.9 | length 13.8
  Top Layer w0.3: MCU.J.1.3 20.892,43.108 ; MCU.U.1.9 19.9,49.46 ccw(c21.01,49.46) 20.225,48.675 ccw(c20.768,49.218) 20.768,48.45 21.698,48.45 cw(c21.698,45.91) 23.494,47.706 ; 20.892,43.108 ccw(c21.575,43.791) 21.575,42.825 22.978,42.825 ccw(c22.978,43.422) 23.4,43 ccw(c22.193,44.207) 23.9,44.207 23.9,46.734 ccw(c22.534,46.734) 23.5,47.7 ; 23.494,47.706 cw(c22.293,46.493) 23.5,47.7 ; 23.494,47.706 23.5,47.7
V_USB: MCU.C.5.2 MCU.C.6.2 MCU.C.7.2 MCU.C.8.2 MCU.C.9.2 MCU.J.1.2 MCU.R.1.2 MCU.R.5.2 MCU.U.1.2 MCU.U.1.7 MCU.U.1.14 MCU.U.1.24 MCU.U.1.34 MCU.U.1.44 MOS.C.10.2 MOS.C.11.2 MOS.D.1.A MOS.R.3.2 MOS.U.2.5 USB.FB.1.2 | length 113.3
  Top Layer w0.35: MCU.C.6.2 ccw(c13.809,47.362) 13.809,46.5 MCU.U.1.14 ; MCU.C.5.2 17.324,37.329 ccw(c18.6,38.605) v1(18.6,36.8) ccw(c17.393,38.007) 18.988,37.4 ccw(c17.393,38.007) 19.1,38.007 MCU.U.1.24 ; MCU.U.1.7 v1(21.5,51.2) ; MCU.U.1.2 v1(25.5,51.4) ; MCU.U.1.34 29.502,40.1 ccw(c29.502,40.945) MCU.C.9.2 ; MCU.U.1.44 29.592,49.642 cw(c30.1,49.134) MCU.C.8.2
  Top Layer w1: MCU.C.7.2 MCU.C.6.2 cw(c14.654,48.207) 12.598,48.207 MCU.R.1.2 ; MCU.R.5.2 30.302,39.859 ccw(c29.611,39.859) MCU.C.9.2 ccw(c30.215,40.463) 30.215,40.3 v1(31.8,40.3)
  Top Layer w1.1: USB.FB.1.2 15.144,8.554 cw(c16.94,10.35) 14.4,10.35 14.4,12.5 cw(c16.94,12.5) 15.144,14.296 17.5,16.652 MOS.C.10.2 ; 17.914,15.425 ccw(c20.249,17.039) 20.24,14.2 cw(c20.246,13.1) 20.246,14.2 21.807,14.2 ccw(c21.81,18.763) 25.039,15.539 26.972,17.472 cw(c35.728,8.719) 35.729,21.1 35.732,21.1 37.046,21.1 ccw(c37.046,23.64) 38.842,21.844 MOS.R.3.2 ; 17.913,15.425 cw(c19.633,16.604) 17.548,16.605 MOS.C.10.2 ; MOS.U.2.5 18.292,20.992 ccw(c20.088,19.195) 17.548,19.195 MOS.C.11.2 MOS.C.10.2
  Bottom Layer w1.1: 13.5,38 11.563,36.063 ccw(c17.743,29.879) 9,29.879 9,29.875 9,24.052 ccw(c11.54,24.052) 9.744,22.256 10.056,21.944 ccw(c11.852,23.74) 11.852,21.2 MOS.U.2.5 ; 31.6,41.5 35.648,41.5 cw(c35.648,38.96) 37.444,40.756 38.656,39.544 cw(c36.86,37.748) 39.4,37.748 39.4,32.507 cw(c37.693,32.507) 38.9,31.3 38.844,31.244 ccw(c40.64,29.448) 38.1,29.448 v3(38.1,24.1)
  other v1: 14.8,46.5 28.6,49.1
pads on no net: MCH.FID.1.1 MCH.FID.2.1 MOS.U.2. USB.J.2.4

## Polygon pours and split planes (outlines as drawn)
GND on Top Layer "GND_L01_P004" (solid, remove dead copper, pour order 4): -1,56 -1,0 44,0 44,56
V_USB on Top Layer "V_USB_L01_P002" (solid, remove dead copper, pour order 2): 37.5,26.6 37.5,19.624 ccw(c38.524,19.624) 37.8,18.9 ccw(c38.041,19.141) 38.041,18.8 39.617,18.8 ccw(c39.617,19.483) 40.1,19 ccw(c39.617,19.483) 40.3,19.483 40.3,25.159 ccw(c39.959,25.159) 40.2,25.4
NetMOS.D.1_C on Top Layer "NETMOS.D.1_C_L01_P001" (solid, remove dead copper, pour order 1): 40.2,34.493 ccw(c38.493,34.493) 39.7,35.7 ccw(c38.734,34.734) 38.734,36.1 37.807,36.1 ccw(c37.807,34.393) 36.6,35.6 ccw(c37.566,34.634) 36.2,34.634 36.2,33.7 ccw(c36.683,33.7) 36.341,33.359 36.9,32.8 cw(c35.451,31.351) 37.5,31.351 37.5,30.1 39.959,30.1 ccw(c39.959,30.441) 40.2,30.2
GND on Bottom Layer "GND_L04_P007" (solid, remove dead copper, pour order 7): 0,55 43,55 43,0 0,0
V_USB on Bottom Layer "V_USB_L04_P003" (solid, remove dead copper, pour order 3): 15,53 26.948,53 cw(c26.948,50.46) 28.744,52.256 32.256,48.744 cw(c30.46,46.948) 33,46.948 33,40.052 cw(c30.46,40.052) 32.256,38.256 30.744,36.744 cw(c28.948,38.54) 28.948,36 15.052,36 cw(c15.052,38.54) 13.256,36.744 12.744,37.256 cw(c14.54,39.052) 12,39.052 12,49.948 cw(c14.54,49.948) 12.744,51.744 13.293,52.293 cw(c15,50.586)
GND on Plane 1 "GND_L02_P005" (solid, remove dead copper, pour order 5): 0,55 43,55 43,0 0,0
GND on Plane 2 "GND_L03_P006" (solid, remove dead copper, pour order 6): 0,55 43,55 43,0 0,0

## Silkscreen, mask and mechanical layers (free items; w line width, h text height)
Top Overlay:
  text "BOOTLOADER" at 33.4,40.023 h1.52
Bottom Overlay:
  text "MiniBall R1.001 January 2021 / Ploopy Corporation / Licensed under CERN OHL v.1.2" at 8,37.6 h2.5 r90
  text "Concealed within his fortress,  / the lord of Mordor sees all.  /  / His gaze pierces cloud,  / shadow, earth, and flesh." at 27.5,2.075 h1.5
Board Outline:
  the board outline again, w0.2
